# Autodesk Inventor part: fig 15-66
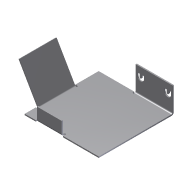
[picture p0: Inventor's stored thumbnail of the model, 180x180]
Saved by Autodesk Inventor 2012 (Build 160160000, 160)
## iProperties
Shininess: 77.0
Angle Display Precision: 2
Document Length Units: 11269
Document Angle Units: 11279
Document Time Units: 11290
Document Mass Units: 11283
Document Length Units Precision: 3
Document Angle Units Precision: 2
Created: 2002-04
Part Number: fig 15-66
Document SubType Name: Sheet Metal
Density: 1 g/cm^3
Sheet Metal Rule: Default
Material: Default
Density: 0.0
Volumn: 0.0
Area: 0.0
PropertySet Name: Model Information
Control State: 0
Master: False
Checked Out: False
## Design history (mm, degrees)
node "Face1"
  sketch "Sketch1"
    geometry: L1 (12.647, 25.882)-(12.647, -14.118); L2 (12.647, -14.118)-(-17.353, -14.118); L3 (-17.353, -14.118)-(-17.353, 15.882); L4 (-17.353, 15.882)-(-2.353, 15.882); L5 (-2.353, 15.882)-(-2.353, 25.882); L6 (-2.353, 25.882)-(12.647, 25.882); 1 further point
    constraints: 12 end point, 4 parallel, 1 perpendicular
    dimensions: "d5" = 30 distance of L2.end L3.end; "d6" = 10 distance of L4.end L5.end; "d7" = 15 distance of L3.end L4.end; "d25" = 15 distance of L5.end L1.start
sketch "Sketch3"
  geometry: L1 (10, -15)-(10, 0)
  constraints: 2 end point
feature "Fold3" sketch "Sketch3" dims "d26" = 0.5 (= BendRadius), "d27" = 90 deg, "d28" = 0.5 (= BendRadius), "d96" = 0.5 (= BendReliefWidth), "d97" = 0.25 (= BendReliefDepth), "d98" = 1 (= MinimumRemnant), "SeamGap" = 0.01, "Thickness" = 0.5
node "Flange2"
sketch "Sketch6"
  geometry: L1 (-6.914, 3.413)-(-5.843, 3.413); L2 (-5.843, 0.624)-(-6.914, 0.624); L3 (-6.914, 2.432)-(-5.843, 2.432); L4 (-5.843, 1.605)-(-6.914, 1.605); L5 (-6.914, 0.624)-(-6.914, 1.605); L6 (-6.914, 2.432)-(-6.914, 3.413); L7 (-6.914, 12.568)-(-6.914, 11.587); L8 (-6.914, 14.376)-(-6.914, 13.395); L9 (-6.914, 11.587)-(-5.843, 11.587); L10 (-5.843, 14.376)-(-6.914, 14.376); L11 (-6.914, 12.568)-(-5.843, 12.568); L12 (-5.843, 13.395)-(-6.914, 13.395); A1 r 1.394 centre (-5.843, 2.018) between (-5.843, 0.624) and (-5.843, 3.413); A2 r 0.413 centre (-5.843, 2.018) between (-5.843, 1.605) and (-5.843, 2.432); A3 r 1.394 centre (-5.843, 12.982) between (-5.843, 11.587) and (-5.843, 14.376); A4 r 0.413 centre (-5.843, 12.982) between (-5.843, 12.568) and (-5.843, 13.395)
  constraints: 24 end point, 8 point on circle, 4 centre point, 3 equal length, 1 perpendicular
cut "Cut1" sketch "Sketch6" dims "d49" = 0.5 (= Thickness), "d50" = 0
node "Flange3"
body "Solid1"
face "Plate1" dims "Thickness" = 0.5
sketch "Sketch5"
  geometry: L1 (20, 0)-(5, 0); L2 (5, 0)-(5, 15); L3 (5, 15)-(20, 15); L4 (20, 15)-(20, 0)
  constraints: 8 end point
face "Plate6" dims "d35" = 10, "d36" = 5, "d38" = 15, "d39" = 60 deg, "d40" = 0.5 (= BendRadius), "Thickness" = 0.5, "MinimumRemnant" = 1 (= 2 x Thickness), "BendReliefWidth" = 0.5 (= Thickness)
bend "Bend5" dims "d38" = 15, "d39" = 60 deg, "d40" = 0.5 (= BendRadius), "d99" = 0.5 (= BendReliefWidth), "d100" = 0.25 (= BendReliefDepth), "d101" = 1 (= MinimumRemnant), "SeamGap" = 0.01, "Thickness" = 0.5, "MinimumRemnant" = 1 (= 2 x Thickness), "BendReliefWidth" = 0.5 (= Thickness), "TransitionRadius" = 0.5 (= BendRadius)
sketch "Sketch7"
  geometry: L1 (25, 0)-(15, 0); L2 (15, 0)-(15, 5); L3 (15, 5)-(25, 5); L4 (25, 5)-(25, 0)
  constraints: 8 end point
face "Plate7" dims "d57" = 5, "d58" = 10, "d60" = 5, "d61" = 90 deg, "d62" = 0.5 (= BendRadius), "Thickness" = 0.5, "MinimumRemnant" = 1 (= 2 x Thickness), "BendReliefWidth" = 0.5 (= Thickness)
bend "Bend7" dims "d59" = 0.5 (= BendRadius), "d60" = 5, "d61" = 90 deg, "d62" = 0.5 (= BendRadius), "d102" = 0.5 (= BendReliefWidth), "d103" = 0.25 (= BendReliefDepth), "d104" = 1 (= MinimumRemnant), "SeamGap" = 0.01, "Thickness" = 0.5, "MinimumRemnant" = 1 (= 2 x Thickness), "BendReliefWidth" = 0.5 (= Thickness)
other parameters: "BendRadius" = 0.5 (= Thickness), "BendReliefDepth" = 0.25 (= 0.5 x Thickness), "CornerReliefSize" = 2 (= 4 x Thickness), "d0" = 0.5 (= BendRadius), "d13" = 0.5 (= BendRadius), "d31" = 0.5 (= BendRadius), "d37" = 0.5 (= BendRadius), "JacobiRadiusSize" = 0.5 (= Thickness), "GapSize" = 0.5 (= Thickness)
